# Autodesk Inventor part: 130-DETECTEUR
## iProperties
Created: 2011-10
Part Number: 130-DETECTEUR
Document SubType Name: Modeling
Designer: A
Manufacturer: Standard
Standards Organization: Custom
Material: Silicium
Author: A
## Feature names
1. Révolution1 [Revolution]
2. Chanfrein1 [Chamfer]
